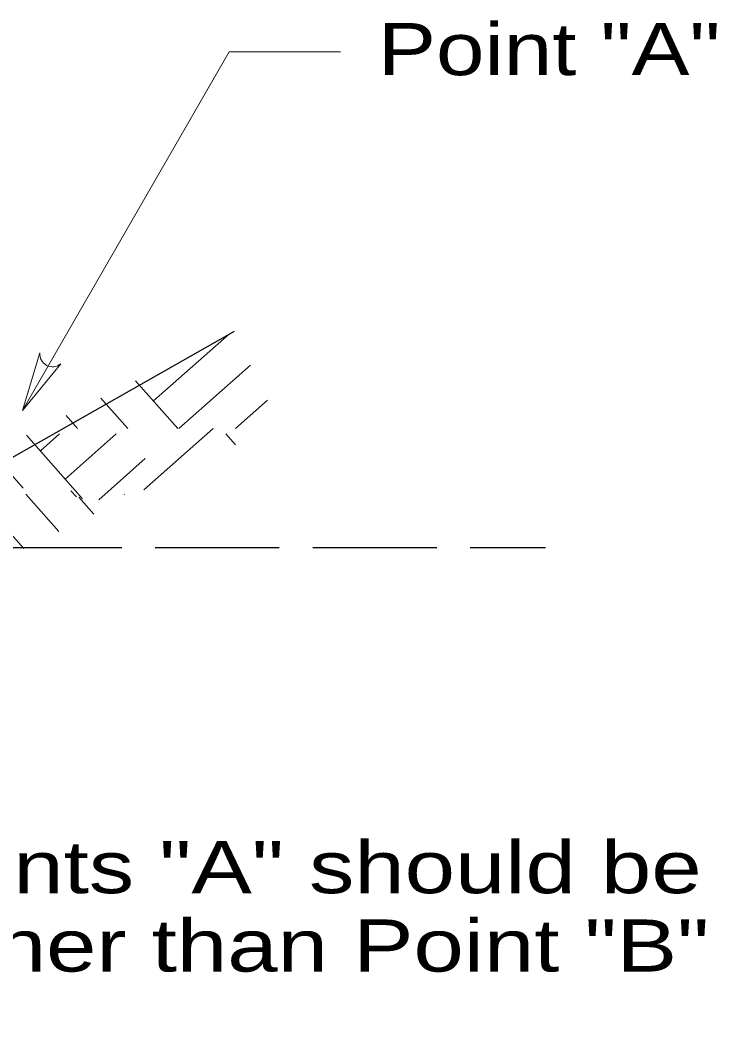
# Model space of a CAD drawing. Extents: x 1083.1 to 1117.1, y 672.5 to 716.5.
# Drawn here: x 1098.058 to 1100.144, y 711.247 to 714.285 of the extents above; entities that cross this region are included whole.
import ezdxf
from ezdxf.enums import TextEntityAlignment as Align

# ---------------------------------------------------------------- set-up
doc = ezdxf.new("R2010")
doc.units = 0
doc.header["$LTSCALE"] = 0.062
doc.linetypes.add('LONG_DASHED', pattern=[7.5, 6, -1.5])
doc.layers.add('1', color=7, linetype='Continuous', lineweight=13)

msp = doc.modelspace()

# ---------------------------------------------------------------- linework, layer by layer
at = {"layer": '1', "lineweight": 25}
msp.add_line((1094.98183, 711.247), (1098.69967, 713.3535), dxfattribs=at)
at = {"layer": '1'}
for p, q in [((1098.45692, 713.14492), (1098.68425, 713.34575)), ((1098.53333, 713.06242), (1098.74808, 713.25225)), ((1098.40342, 713.20542), (1098.52992, 713.06242)), ((1098.29933, 713.15333), (1098.37975, 713.06242)), ((1098.703, 713.06242), (1098.7985, 713.14683)), ((1098.19508, 713.10125), (1098.22942, 713.06242)), ((1098.11808, 712.99525), (1098.17558, 713.04608)), ((1098.19258, 712.91108), (1098.34517, 713.046)), ((1098.4285, 712.87892), (1098.63592, 713.06242)), ((1098.674, 713.04617), (1098.703, 713.01333)), ((1098.07692, 713.04217), (1098.24467, 712.85225)), ((1097.97275, 712.99008), (1098.06667, 712.88367)), ((1098.293, 712.84925), (1098.43233, 712.97258)), ((1097.9155, 712.87583), (1098.06875, 712.70267)), ((1098.07467, 712.86608), (1098.17375, 712.75408)), ((1098.20975, 712.87592), (1098.226, 712.85758)), ((1098.36883, 712.86608), (1098.36992, 712.86483)), ((1098.23342, 712.85642), (1098.2785, 712.80542))]:
    msp.add_line(p, q, dxfattribs=at)
at = {"layer": '1', "linetype": 'LONG_DASHED', "lineweight": 25}
msp.add_line((1087.134, 712.706), (1099.63158, 712.706), dxfattribs=at)
at = {"layer": '1'}
for points in [[(1098.065, 713.11625), (1098.68358, 714.19008), (1099.0175, 714.19008)], [(1098.17925, 713.25608), (1098.065, 713.11625), (1098.11667, 713.28925), (1098.11675, 713.28917)]]:
    msp.add_lwpolyline(points, dxfattribs=at)
msp.add_arc((1098.15478, 713.28531), 0.0382, 174.14768, 309.97381, dxfattribs=at)

# ---------------------------------------------------------------- texts
at = {"layer": '1', "width": 1.25}
msp.add_text('Point "A"', height=0.156, dxfattribs=at).set_placement((1099.1295, 714.12067))
at = {"layer": '1', "width": 1.3}
for s, p in [('Points "A" should be', (1098.87217, 711.67075)), ('higher than Point "B"', (1098.87217, 711.43608))]:
    msp.add_text(s, height=0.156, dxfattribs=at).set_placement(p, align=Align.CENTER)

doc.saveas('drawing.dxf')
